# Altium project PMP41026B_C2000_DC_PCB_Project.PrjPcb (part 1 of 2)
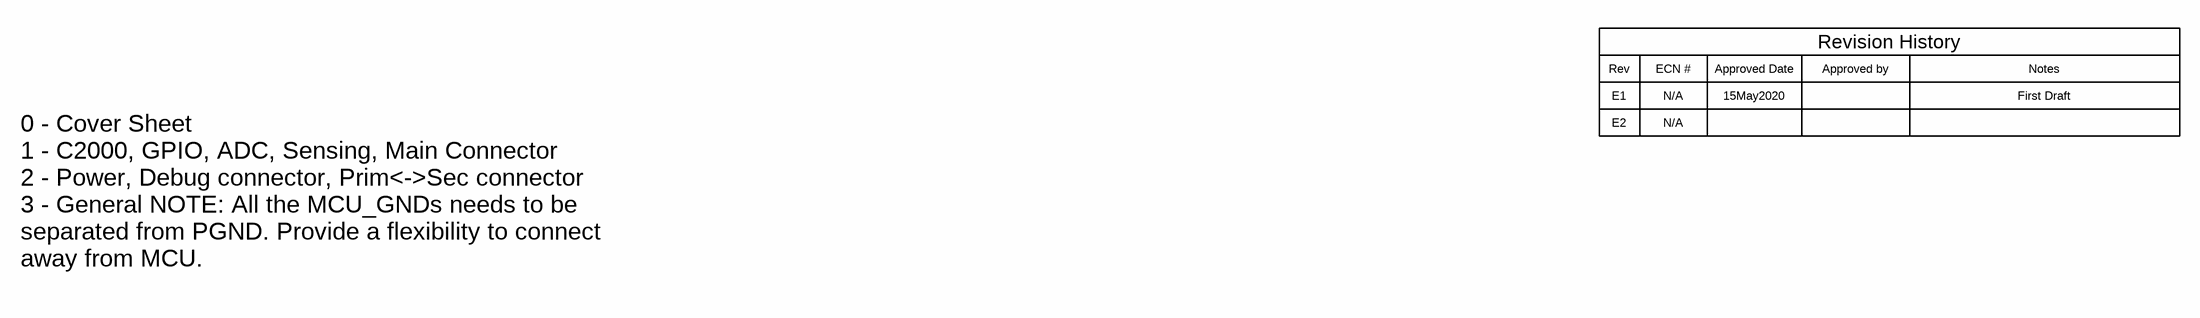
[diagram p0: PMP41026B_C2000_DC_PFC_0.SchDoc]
CopyrightYear: 2024; PCB_Layout: Richard Yin; PCB_Rev: B; PRJ_Customer: Public Release; PRJ_Engineer: Enter name of project lead; PRJ_Number: PMP41026B; PRJ_Title: Change in menu Project|Project Options|Parameters; SCH_Rev: B; TechSupport: http://www.ti.com/support; TID: N/A
5 sheets, 261 parts. Net scope: global (net labels, ports and power ports of the same name join across sheets).
Board file: PMP41026B_C2000_DC.PcbDoc
Sheets:
  PMP41026B_C2000_DC_PFC_0.SchDoc
  PMP41026B_C2000_DC_PFC_1.SchDoc
  PMP41026B_C2000_DC_PFC_2.SchDoc
  PMP41026B_C2000_DC_LLC_Control.SchDoc
  PMP41026B_C2000_DC_LLC_F280039C.SchDoc

## Sheet PMP41026B_C2000_DC_PFC_0.SchDoc: Cover Sheet
size 431 x 279 mm; Date: Not shown in title block; ApprovedBy: Not shown in title block; CheckedBy: Not shown in title block; Author: Not shown in title block; CompanyName: Not shown in title block; DrawnBy: San Chen; Engineer: Not shown in title block; Organization: Not shown in title block; Address1: Not shown in title block; Address2: Not shown in title block; Address3: Not shown in title block; Address4: Not shown in title block; DocumentNumber: 1; Revision: Use project parameter SCH_Rev; SheetNumber: 1; SheetTotal: 9; PageSetup: Record=PageOptions¦CenterHorizontal=True¦CenterVertical=True¦PrintScale=1.00¦XCorrection=1.00¦YCorrection=1.00¦PrintKind=0¦BorderSize=5000000¦LeftOffset=0¦BottomOffset=0¦Orientation=2¦PaperLength=1000¦PaperWidth=1000¦Scale=100¦PaperSource=15¦PrintQuality=600¦MediaType=1¦DitherType=10¦PaperKind=Letter¦PrintScaleMode=1

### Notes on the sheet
- Rev
- E1
- ECN #
- N/A
- Approved Date
- 15May2020
- Approved by
- Revision History
- Notes
- First Draft
- E2
- 0 - Cover Sheet
  1 - C2000, GPIO, ADC, Sensing, Main Connector
  2 - Power, Debug connector, Prim<->Sec connector
  3 - General NOTE: All the MCU_GNDs needs to be separated from PGND. Provide a flexibility to connect away from MCU.

## Sheet PMP41026B_C2000_DC_PFC_1.SchDoc: ADC
size 431 x 279 mm; Date: Not shown in title block; ApprovedBy: Not shown in title block; CheckedBy: Not shown in title block; Author: Not shown in title block; CompanyName: Not shown in title block; DrawnBy: San Chen; Engineer: Not shown in title block; Organization: Not shown in title block; Address1: Not shown in title block; Address2: Not shown in title block; Address3: Not shown in title block; Address4: Not shown in title block; DocumentNumber: 2; Revision: Use project parameter SCH_Rev; SheetNumber: 2; SheetTotal: 5; PageSetup: Record=PageOptions¦CenterHorizontal=True¦CenterVertical=True¦PrintScale=1.00¦XCorrection=1.00¦YCorrection=1.00¦PrintKind=0¦BorderSize=5000000¦LeftOffset=0¦BottomOffset=0¦Orientation=2¦PaperLength=1000¦PaperWidth=1000¦Scale=100¦PaperSource=15¦PrintQuality=600¦MediaType=1¦DitherType=10¦PaperKind=Letter¦PrintScaleMode=1
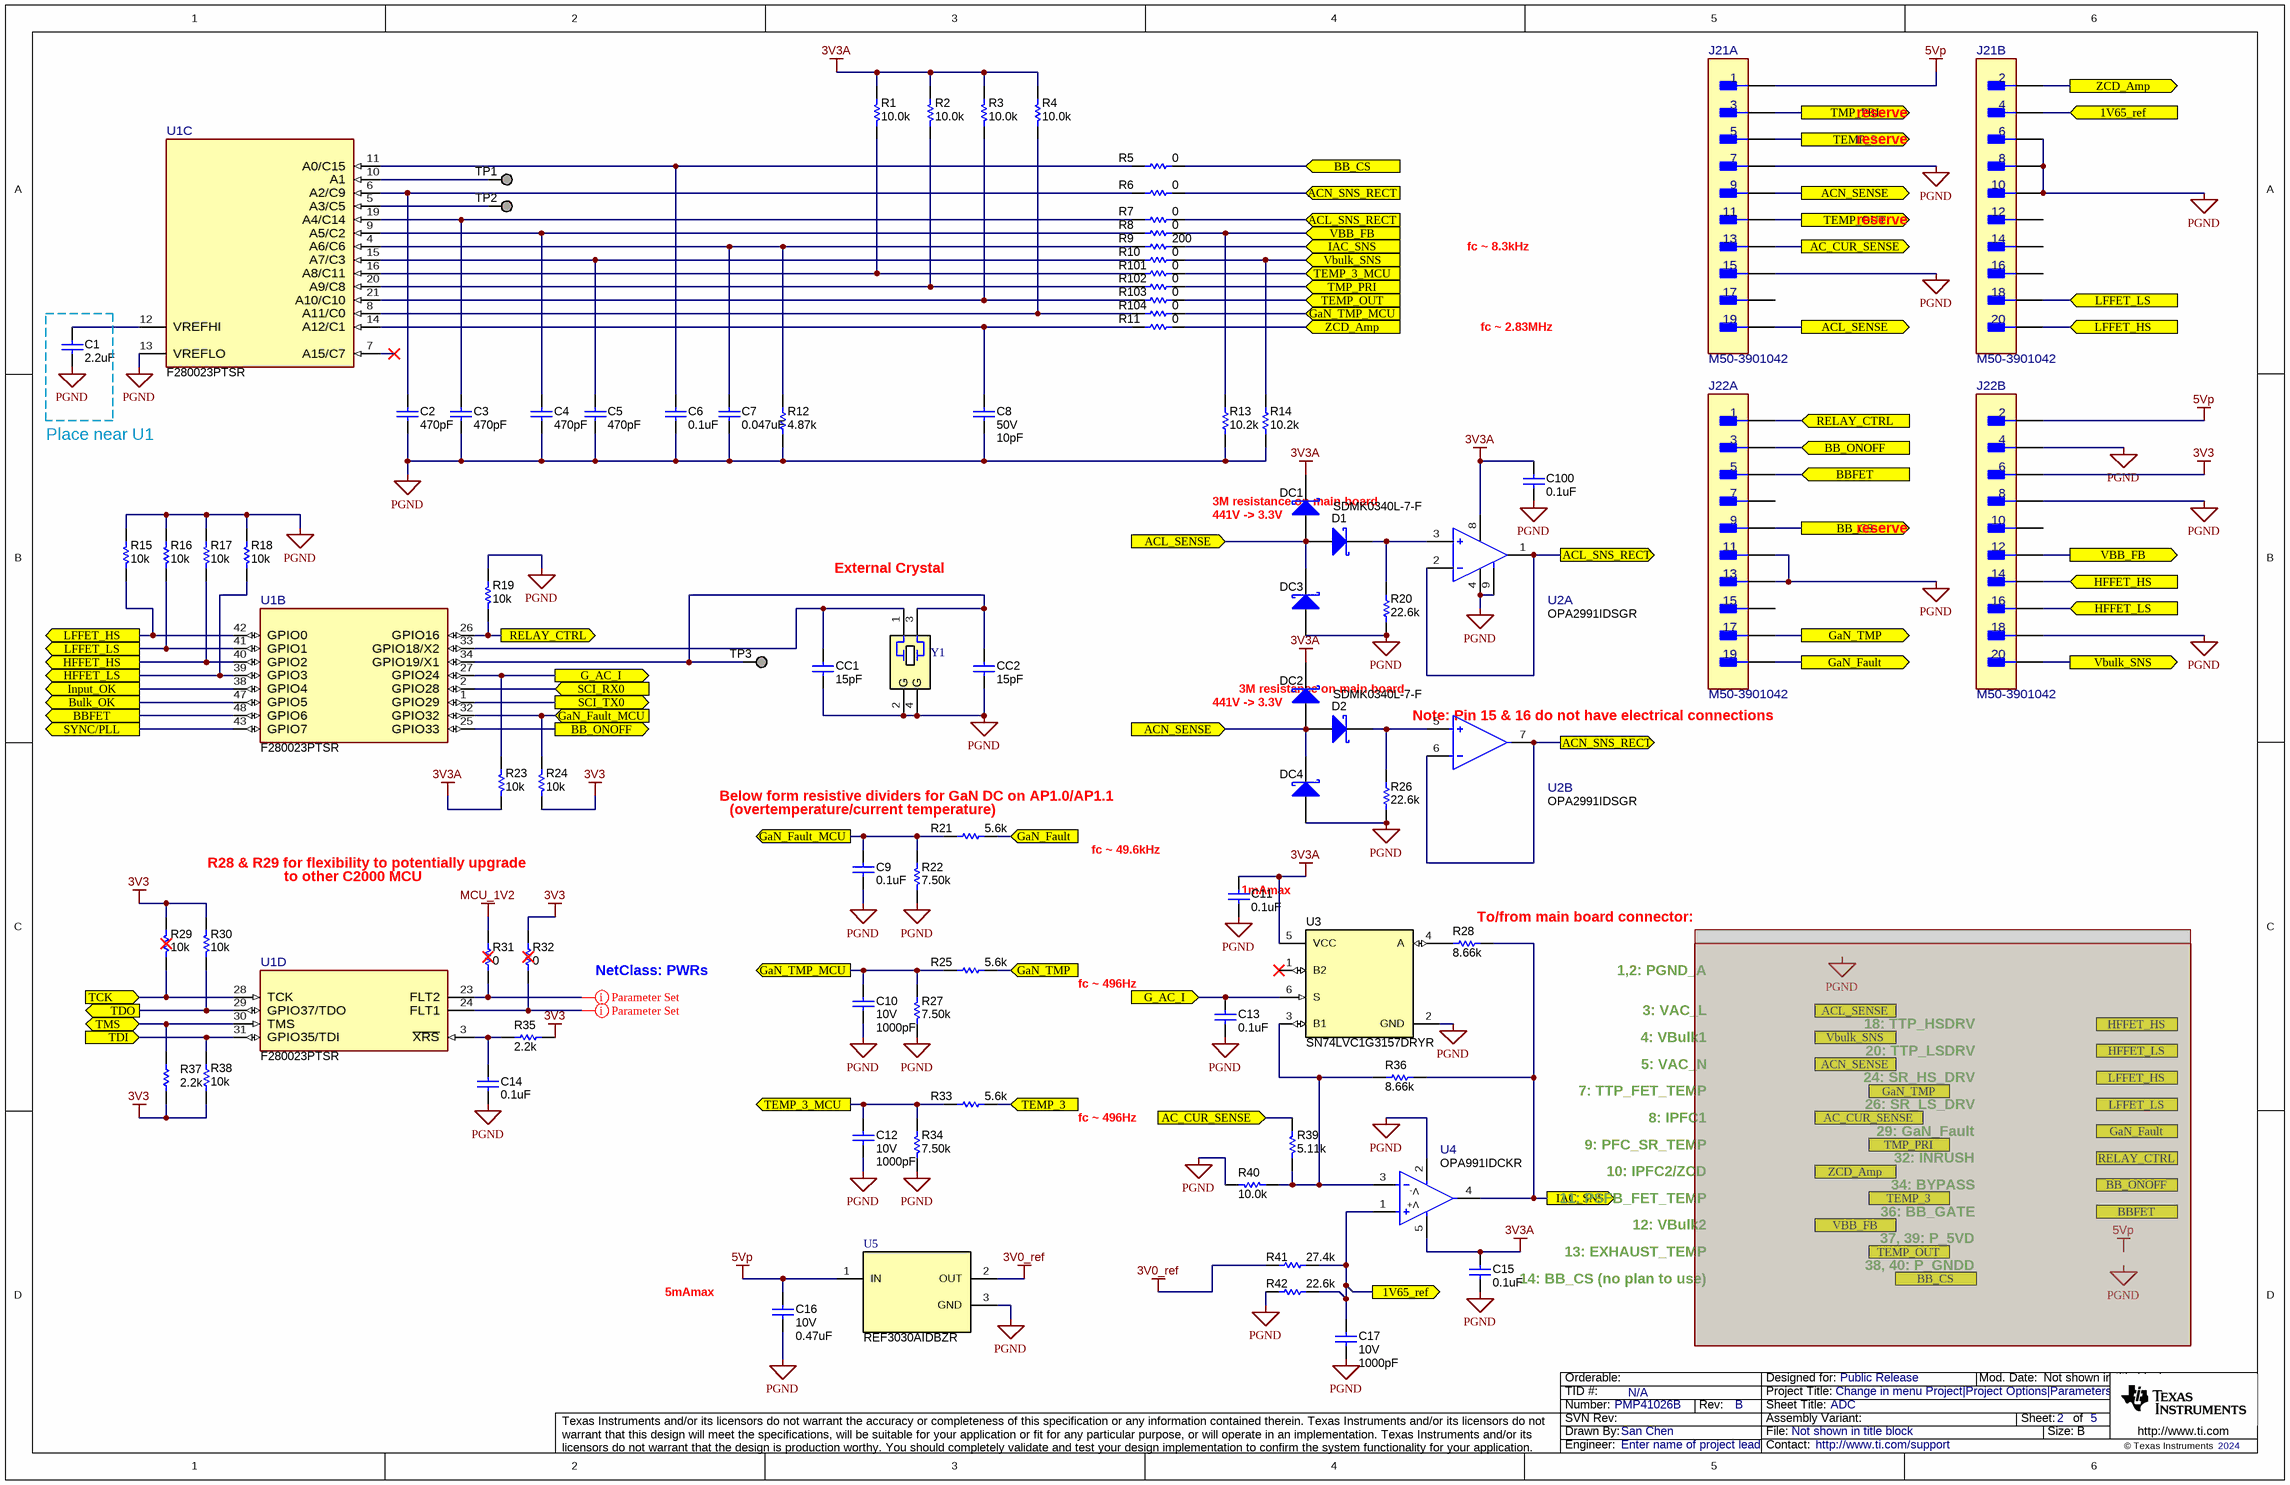
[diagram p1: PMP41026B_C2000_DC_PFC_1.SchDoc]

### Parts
C1  ValueDisplayed: 2.2uF  [0603]  (hidden comment: C0603C225K8PACTU)
C2  ValueDisplayed: 470pF  [0402]  (hidden comment: CGA2B2X7R1H471K050BA)
C3  ValueDisplayed: 470pF  [0402]  (hidden comment: CGA2B2X7R1H471K050BA)
C4  ValueDisplayed: 470pF  [0402]  (hidden comment: CGA2B2X7R1H471K050BA)
C5  ValueDisplayed: 470pF  [0402]  (hidden comment: CGA2B2X7R1H471K050BA)
C6  ValueDisplayed: 0.1uF  [0402]  (hidden comment: GRM155R60J104KA01D)
C7  ValueDisplayed: 0.047uF  [0402]  (hidden comment: C1005X5R1A473K050BA)
C8  VDC_V: 50V  ValueDisplayed: 10pF  [0402]  (hidden comment: 04025U100CAT2A)
C9  ValueDisplayed: 0.1uF  [0402]  (hidden comment: GRM155R60J104KA01D)
C10  VDC_V: 10V  ValueDisplayed: 1000pF  [0402]  (hidden comment: GRM155R61A102KA01D)
C11  ValueDisplayed: 0.1uF  [0402]  (hidden comment: GRM155R71A104KA01D)
C12  VDC_V: 10V  ValueDisplayed: 1000pF  [0402]  (hidden comment: GRM155R61A102KA01D)
C13  ValueDisplayed: 0.1uF  [0402]  (hidden comment: GCM155R71C104KA55D)
C14  ValueDisplayed: 0.1uF  [0402]  (hidden comment: GRM155R60J104KA01D)
C15  ValueDisplayed: 0.1uF  [0402]  (hidden comment: GRM155R60J104KA01D)
C16  VDC_V: 10V  ValueDisplayed: 0.47uF  [0402]  (hidden comment: GCM155C71A474KE36D)
C17  VDC_V: 10V  ValueDisplayed: 1000pF  [0402]  (hidden comment: GRM155R61A102KA01D)
C100  ValueDisplayed: 0.1uF  [0402]  (hidden comment: GRM155R71A104KA01D)
CC1  ValueDisplayed: 15pF  [0402]  (hidden comment: 885012005056)
CC2  ValueDisplayed: 15pF  [0402]  (hidden comment: 885012005056)
D1  SDMK0340L-7-F  [SOD-323]
D2  SDMK0340L-7-F  [SOD-323]
DC1  SDMK0340L-7-F  [SOD-323]  (value not drawn)
DC2  SDMK0340L-7-F  [SOD-323]  (value not drawn)
DC3  SDMK0340L-7-F  [SOD-323]  (value not drawn)
DC4  SDMK0340L-7-F  [SOD-323]  (value not drawn)
J21  M50-3901042  [FP-M50-3901042_HDR20-MFG]  (parts A,B of 2)
J22  M50-3901042  [FP-M50-3901042_HDR20-MFG]  (parts A,B of 2)
R1  ValueDisplayed: 10.0k  [0402]  (hidden comment: CRCW040210K0FKED)
R2  ValueDisplayed: 10.0k  [0402]  (hidden comment: CRCW040210K0FKED)
R3  ValueDisplayed: 10.0k  [0402]  (hidden comment: CRCW040210K0FKED)
R4  ValueDisplayed: 10.0k  [0402]  (hidden comment: CRCW040210K0FKED)
R5  ValueDisplayed: 0  [0402]  (hidden comment: CRCW04020000Z0ED)
R6  ValueDisplayed: 0  [0402]  (hidden comment: CRCW04020000Z0ED)
R7  ValueDisplayed: 0  [0402]  (hidden comment: CRCW04020000Z0ED)
R8  ValueDisplayed: 0  [0402]  (hidden comment: CRCW04020000Z0ED)
R9  ValueDisplayed: 200  [0402]  (hidden comment: CRCW0402200RJNED)
R10  ValueDisplayed: 0  [0402]  (hidden comment: CRCW04020000Z0ED)
R11  ValueDisplayed: 0  [0402]  (hidden comment: CRCW04020000Z0ED)
R12  ValueDisplayed: 4.87k  [0402]  (hidden comment: ERA-2AEB4871X)
R13  ValueDisplayed: 10.2k  [0402]  (hidden comment: CRCW040210K2FKED)
R14  ValueDisplayed: 10.2k  [0402]  (hidden comment: CRCW040210K2FKED)
R15  ValueDisplayed: 10k  [0402]  (hidden comment: CRCW040210K0JNED)
R16  ValueDisplayed: 10k  [0402]  (hidden comment: CRCW040210K0JNED)
R17  ValueDisplayed: 10k  [0402]  (hidden comment: CRCW040210K0JNED)
R18  ValueDisplayed: 10k  [0402]  (hidden comment: CRCW040210K0JNED)
R19  ValueDisplayed: 10k  [0402]  (hidden comment: CRCW040210K0JNED)
R20  ValueDisplayed: 22.6k  [0402]  (hidden comment: CRCW040222K6FKED)
R21  ValueDisplayed: 5.6k  [0402]  (hidden comment: CRCW04025K60JNED)
R22  ValueDisplayed: 7.50k  [0402]  (hidden comment: CRCW04027K50FKED)
R23  ValueDisplayed: 10k  [0402]  (hidden comment: CRCW040210K0JNED)
R24  ValueDisplayed: 10k  [0402]  (hidden comment: CRCW040210K0JNED)
R25  ValueDisplayed: 5.6k  [0402]  (hidden comment: CRCW04025K60JNED)
R26  ValueDisplayed: 22.6k  [0402]  (hidden comment: CRCW040222K6FKED)
R27  ValueDisplayed: 7.50k  [0402]  (hidden comment: CRCW04027K50FKED)
R28  ValueDisplayed: 8.66k  [0402]  (hidden comment: CRCW04028K66FKED)
R29  ValueDisplayed: 10k  [0402]  (hidden comment: CRCW040210K0JNED)
R30  ValueDisplayed: 10k  [0402]  (hidden comment: CRCW040210K0JNED)
R31  ValueDisplayed: 0  [0402]  (hidden comment: CRCW04020000Z0ED)
R32  ValueDisplayed: 0  [0402]  (hidden comment: CRCW04020000Z0ED)
R33  ValueDisplayed: 5.6k  [0402]  (hidden comment: CRCW04025K60JNED)
R34  ValueDisplayed: 7.50k  [0402]  (hidden comment: CRCW04027K50FKED)
R35  ValueDisplayed: 2.2k  [0402]  (hidden comment: CRCW04022K20JNED)
R36  ValueDisplayed: 8.66k  [0402]  (hidden comment: CRCW04028K66FKED)
R37  ValueDisplayed: 2.2k  [0402]  (hidden comment: CRCW04022K20JNED)
R38  ValueDisplayed: 10k  [0402]  (hidden comment: CRCW040210K0JNED)
R39  ValueDisplayed: 5.11k  [0402]  (hidden comment: CRCW04025K11FKED)
R40  ValueDisplayed: 10.0k  [0402]  (hidden comment: CRCW040210K0FKED)
R41  ValueDisplayed: 27.4k  [0402]  (hidden comment: CRCW040227K4FKED)
R42  ValueDisplayed: 22.6k  [0402]  (hidden comment: CRCW040222K6FKED)
R101  ValueDisplayed: 0  [0402]  (hidden comment: CRCW04020000Z0ED)
R102  ValueDisplayed: 0  [0402]  (hidden comment: CRCW04020000Z0ED)
R103  ValueDisplayed: 0  [0402]  (hidden comment: CRCW04020000Z0ED)
R104  ValueDisplayed: 0  [0402]  (hidden comment: CRCW04020000Z0ED)
TP1  TP_H0.45P0.75  [TP_H045P075]  (value not drawn)  (no BOM)
TP2  TP_H0.45P0.75  [TP_H045P075]  (value not drawn)  (no BOM)
TP3  TP_H0.45P0.75  [TP_H045P075]  (value not drawn)  (no BOM)
U1  F280023PTSR  [PT0048A-IPC_C]  (parts B,C,D of 4)
U2  OPA2991IDSGR  [DSG0008A-MFG]  (parts A,B of 2)
U3  SN74LVC1G3157DRYR  [DRY0006A]
U4  OPA991IDCKR  [DCK0005A-MFG]
U5  REF3030AIDBZR  [DBZ0003A_N]
Y1  ECS-200-18-30B-AGN-TR  [ECS_ECX-53B]  (value not drawn)

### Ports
1V65_ref (in), 1V65_ref (out), AC_CUR_SENSE (in), AC_CUR_SENSE (out), ACL_SENSE (in), ACL_SENSE (out), ACL_SNS_RECT (in), ACL_SNS_RECT (out), ACN_SENSE (in), ACN_SENSE (out), ACN_SNS_RECT (in), ACN_SNS_RECT (out), BB_CS (in), BB_CS (out), BB_ONOFF (in), BB_ONOFF (out), BBFET (in), BBFET (out), Bulk_OK (out), G_AC_I (in), G_AC_I (out), GaN_Fault (in), GaN_Fault (out), GaN_Fault_MCU (in), GaN_Fault_MCU (out), GaN_TMP (in), GaN_TMP (out), GaN_TMP_MCU (in), GaN_TMP_MCU (out), HFFET_HS (in), HFFET_HS (out), HFFET_LS (in), HFFET_LS (out), IAC_SNS (in), IAC_SNS (out), Input_OK (out), LFFET_HS (in), LFFET_HS (out), LFFET_LS (in), LFFET_LS (out), RELAY_CTRL (in), RELAY_CTRL (out), SCI_RX0 (in), SCI_TX0 (out), SYNC/PLL (out), TCK (in), TDI (in), TDO (out), TEMP_3 (in), TEMP_3 (out), TEMP_3_MCU (in), TEMP_3_MCU (out), TEMP_OUT (in), TEMP_OUT (out), TMP_PRI (in), TMP_PRI (out), TMS (bidir), VBB_FB (in), VBB_FB (out), Vbulk_SNS (in), Vbulk_SNS (out), ZCD_Amp (in), ZCD_Amp (out)

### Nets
3V0_ref: R41.1 U5.2(OUT)
3V3: J22.6 R24.2 R29.1 R30.1 R32.2 R35.1 R37.1 R38.2
3V3A: C11.1 C15.2 C100.1 DC1.1(K) DC2.1(K) R1.2 R2.2 R3.2 R4.2 R23.2 U2.8(V+) U3.5(VCC) U4.5(V+)
5Vp: C16.1 J21.1 J22.2 U5.1(IN)
MCU_1V2: R31.2
PGND: C1.1 C2.2 C3.2 C4.2 C5.2 C6.1 C7.2 C8.2 C9.1 C10.2 C11.2 C12.2 C13.2 C14.1 C15.1 C16.2 C17.2 C100.2 CC1.2 CC2.2 DC3.2(A) DC4.2(A) J21.6 J21.7 J21.8 J21.10 J21.15 J22.4 J22.8 J22.11 J22.13 J22.18 R12.1 R13.1 R14.1 R15.1 R16.1 R17.1 R18.1 R19.1 R20.1 R22.1 R26.1 R27.1 R34.1 R40.2 R42.2 U1.13(VREFLO) U2.4(V-) U2.9(Thermal_Pad) U3.2(GND) U4.2(V-) U5.3(GND) Y1.2(GND) Y1.4(GND)
1V65_ref: C17.1 J21.4 R41.2 R42.1 U4.1(IN+) ; port 1V65_ref
AC_CUR_SENSE: J21.13 R39.1 ; port AC_CUR_SENSE
ACL_SENSE: D1.2(A) DC1.2(A) DC3.1(K) J21.19 ; port ACL_SENSE
ACL_SNS_RECT: R7.2 U2.1(OUT1) U2.2(IN1-) ; port ACL_SNS_RECT
ACN_SENSE: D2.2(A) DC2.2(A) DC4.1(K) J21.9 ; port ACN_SENSE
ACN_SNS_RECT: R6.2 U2.6(IN2-) U2.7(OUT2) ; port ACN_SNS_RECT
BB_CS: J22.9 R5.2 ; port BB_CS
BB_ONOFF: J22.3 U1.25(GPIO33) ; port BB_ONOFF
BBFET: J22.5 U1.48(GPIO6) ; port BBFET
Bulk_OK: U1.47(GPIO5) ; port Bulk_OK
G_AC_I: C13.1 R23.1 U1.27(GPIO24) U3.6(S) ; port G_AC_I
GaN_Fault: J22.19 R21.2 ; port GaN_Fault
GaN_Fault_MCU: C9.2 R21.1 R22.2 R24.1 U1.32(GPIO32) ; port GaN_Fault_MCU
GaN_TMP: J22.17 R25.2 ; port GaN_TMP
GaN_TMP_MCU: C10.1 R25.1 R27.2 R104.2 ; port GaN_TMP_MCU
HFFET_HS: J22.14 R17.2 U1.40(GPIO2) ; port HFFET_HS
HFFET_LS: J22.16 R18.2 U1.39(GPIO3) ; port HFFET_LS
IAC_SNS: R9.2 R28.2 R36.2 U4.4(OUT) ; port IAC_SNS
Input_OK: U1.38(GPIO4) ; port Input_OK
LFFET_HS: J21.20 R15.2 U1.42(GPIO0) ; port LFFET_HS
LFFET_LS: J21.18 R16.2 U1.41(GPIO1) ; port LFFET_LS
RELAY_CTRL: J22.1 R19.2 U1.26(GPIO16) ; port RELAY_CTRL
SCI_RX0: U1.2(GPIO28) ; port SCI_RX0
SCI_TX0: U1.1(GPIO29) ; port SCI_TX0
SYNC/PLL: U1.43(GPIO7) ; port SYNC/PLL
TCK: R29.2 U1.28(TCK) ; port TCK
TDI: R38.1 U1.31(GPIO35/TDI) ; port TDI
TDO: R30.2 U1.29(GPIO37/TDO) ; port TDO
TEMP_3: J21.5 R33.2 ; port TEMP_3
TEMP_3_MCU: C12.1 R33.1 R34.2 R101.2 ; port TEMP_3_MCU
TEMP_OUT: J21.11 R103.2 ; port TEMP_OUT
TMP_PRI: J21.3 R102.2 ; port TMP_PRI
TMS: R37.2 U1.30(TMS) ; port TMS
VBB_FB: J22.12 R8.2 R13.2 ; port VBB_FB
Vbulk_SNS: J22.20 R10.2 R14.2 ; port Vbulk_SNS
ZCD_Amp: J21.2 R11.2 ; port ZCD_Amp
NetC1_2: C1.2 U1.12(VREFHI)
NetC2_1: C2.1 R6.1 U1.6(A2/C9)
NetC3_1: C3.1 R7.1 U1.19(A4/C14)
NetC4_1: C4.1 R8.1 U1.9(A5/C2)
NetC5_1: C5.1 R10.1 U1.15(A7/C3)
NetC6_2: C6.2 R5.1 U1.11(A0/C15)
NetC7_1: C7.1 R9.1 R12.2 U1.4(A6/C6)
NetC8_1: C8.1 R11.1 U1.14(A12/C1)
NetC14_2: C14.2 R35.2 U1.3(~{XRS})
NetCC1_1: CC1.1 U1.33(GPIO18/X2) Y1.1
NetCC2_1: CC2.1 TP3.1 U1.34(GPIO19/X1) Y1.3
NetD1_1: D1.1(K) R20.2 U2.3(IN1+)
NetD2_1: D2.1(K) R26.2 U2.5(IN2+)
NetR1_1: R1.1 R101.1 U1.16(A8/C11)
NetR2_1: R2.1 R102.1 U1.20(A9/C8)
NetR3_1: R3.1 R103.1 U1.21(A10/C10)
NetR4_1: R4.1 R104.1 U1.8(A11/C0)
NetR28_1: R28.1 U3.4(A)
NetR31_1: R31.1 U1.23(FLT2)
NetR32_1: R32.1 U1.24(FLT1)
NetR36_1: R36.1 R39.2 R40.1 U3.3(B1) U4.3(IN-)
NetTP1_1: TP1.1 U1.10(A1)
NetTP2_1: TP2.1 U1.5(A3/C5)

Not connected (* = marked no-connect by the designer): J21 12 14 16 17; J22 7 10 15; U1 7(A15/C7)*; U3 1(B2)*

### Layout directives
net class PWRs: NetR31_1, NetR32_1

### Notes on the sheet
- reserve
- fc ~ 8.3kHz
- fc ~ 2.83MHz
- Place near U1
- 3M resistance on main board
- External Crystal
- 441V -> 3.3V
- (near J22) Note: Pin 15 & 16 do not have electrical connections
- (near R21) (overtemperature/current temperature)
- (near R21) Below form resistive dividers for GaN DC on AP1.0/AP1.1
- to other C2000 MCU
- R28 & R29 for flexibility to potentially upgrade
- (near R21) fc ~ 49.6kHz
- 1mAmax
- NetClass: PWRs
- To/from main board connector:
- 1,2: PGND_A
- (near R25) fc ~ 496Hz
- 3: VAC_L
- 4: VBulk1
- 18: TTP_HSDRV
- 5: VAC_N
- 7: TTP_FET_TEMP
- 20: TTP_LSDRV
- 24: SR_HS_DRV
- 26: SR_LS_DRV
- (near R33) fc ~ 496Hz
- 8: IPFC1
- 9: PFC_SR_TEMP
- 10: IPFC2/ZCD
- 32: INRUSH
- 29: GaN_Fault
- 11: PSFB_FET_TEMP
- 12: VBulk2
- 34: BYPASS
- 36: BB_GATE
- 37, 39: P_5VD
- (near C16) 5mAmax
- 13: EXHAUST_TEMP
- 14: BB_CS (no plan to use)
- 38, 40: P_GNDD

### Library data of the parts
C1 = CMP-0006906-5: CAP, CERM, 2.2 uF, 10 V, +/- 10%, X5R, 0603; Manufacturer: Kemet; TaMin_C: -55°C; Polarized: N; SizeAreaWB_mm2: 4.68; Value1: Unknown; U/M: EA; Value: 2.2uF; TaMax_C: 85°C; SizeZ_mm: 1; SizeX_mm: 1.6; SizeY_mm: 0.8; Value2: 10V; SizeArea_mm2: 1.28; CompType: Capacitor; Cap_F: 2.2µF; AEC Category: Q200
C2-C5 = CMP-0006320-2: CAP, CERM, 470 pF, 50 V, +/- 10%, X7R, AEC-Q200 Grade 1, 0402; Manufacturer: TDK; TaMin_C: -55°C; ESR_ohm: 4.96489; Polarized: N; SizeAreaWB_mm2: 3; Value1: 4.96489 ohm; U/M: EA; Value: 470pF; TaMax_C: 125°C; SizeZ_mm: 0.6; SizeX_mm: 1; SizeY_mm: 0.5; Value2: 50V; CompType: Capacitor; AEC Qualified: Y; IRMS_A: 2.28414dA; AEC Category: Q200
C6 C9 C14 C15 = CMP-0006531-2: CAP, CERM, 0.1 uF, 6.3 V, +/- 10%, X5R, 0402; Manufacturer: MuRata; Polarized: N; Value: 0.1uF; U/M: EA; Cap_F: 100nF; Value1: Unknown; VDC_V: 6.3V; TaMin_C: -55°C; TaMax_C: 85°C; AEC Category: Q200; SizeArea_mm2: 0.5; SizeAreaWB_mm2: 3; SizeX_mm: 1; SizeZ_mm: 0.6
C7 = CMP-0006266-2: CAP, CERM, 0.047 uF, 10 V, +/- 10%, X5R, 0402; Manufacturer: TDK; Polarized: N; U/M: EA; Cap_F: 47nF; Value1: Unknown; VDC_V: 10V; TaMin_C: -55°C; TaMax_C: 85°C; SizeArea_mm2: 0.5; SizeAreaWB_mm2: 3; SizeX_mm: 1; SizeZ_mm: 0.6; AEC Category: Q200
C8 = CMP-0064911-2: CAP, CERM, 10 pF, 50 V,+/- 2.5%, C0G/NP0, AEC-Q200 Grade 1, 0402; Manufacturer: AVX; TaMin_C: -55°C; Polarized: N; SizeAreaWB_mm2: 3; Value1: Unknown; U/M: EA; Value: 10pF; TaMax_C: 125°C; SizeZ_mm: 0.6; SizeX_mm: 1; SizeY_mm: 0.5; AEC Qualified: Y; AEC Category: Q200
C10 C12 C17 = CMP-0006560-2: CAP, CERM, 1000 pF, 10 V, +/- 10%, X5R, 0402; Manufacturer: MuRata; TaMin_C: -55°C; Polarized: N; SizeAreaWB_mm2: 3; Value1: Unknown; U/M: EA; Value: 1000pF; TaMax_C: 85°C; SizeZ_mm: 0.6; SizeX_mm: 1; SizeY_mm: 0.5; Cap_F: 1nF; AEC Category: Q200
C11 C100 = CMP-0006629-2: CAP, CERM, 0.1 uF, 10 V, +/- 10%, X7R, 0402; Manufacturer: MuRata; Polarized: N; Value: 0.1uF; U/M: EA; Cap_F: 100nF; Value1: Unknown; VDC_V: 10V; TaMin_C: -55°C; TaMax_C: 125°C; SizeArea_mm2: 0.5; SizeAreaWB_mm2: 3; SizeX_mm: 1; SizeZ_mm: 0.6; AEC Category: Q200
C13 = CMP-0006351-2: CAP, CERM, 0.1 uF, 16 V, +/- 10%, X7R, 0402; Manufacturer: MuRata; Polarized: N; Value: 0.1uF; U/M: EA; Cap_F: 100nF; Value1: Unknown; VDC_V: 16V; TaMin_C: -55°C; TaMax_C: 125°C; SizeArea_mm2: 0.5; SizeAreaWB_mm2: 3; SizeX_mm: 1; SizeZ_mm: 0.6; AEC Category: Q200
C16 = CMP-0064967-2: CAP, CERM, 0.47 uF, 10 V,+/- 10%, X7S, 0402; Manufacturer: MuRata; TaMin_C: -55°C; Polarized: N; SizeAreaWB_mm2: 3; Value1: Unknown; U/M: EA; Value: 0.47uF; TaMax_C: 125°C; SizeZ_mm: 0.6; SizeX_mm: 1; SizeY_mm: 0.5; Cap_F: 470nF; AEC Category: Q200
CC1 CC2 = CMP-0006216-2: CAP, CERM, 15 pF, 50 V, +/- 5%, C0G/NP0, 0402; Manufacturer: Wurth Elektronik; Polarized: N; Value: 15pF; U/M: EA; Value1: Unknown; VDC_V: 50V; TaMin_C: -55°C; TaMax_C: 125°C; AEC Category: Q200; SizeArea_mm2: 0.5; SizeAreaWB_mm2: 3; SizeX_mm: 1; SizeZ_mm: 0.6
D1 D2 DC1-DC4 = CMP-0028573-2: Diode, Schottky, 40 V, 0.03 A, SOD-323; Manufacturer: Diodes Inc.; Vf_V: 1V; SizeArea_mm2: 3.645; Vr_V: 40V; SizeAreaWB_mm2: 8.695; Io_A: 30mA; Value1: 0.03A; Green_Lifecycle: Not Set; SizeZ_mm: 1; SizeY_mm: 1.35; Value: 40V; SizeX_mm: 2.7; AEC Category: Q101; Green_REACh: Incomplete
J21 J22 = CMP-0122579-1: Connector Header Through Hole, Right Angle 20 position 0.050" (1.27mm); Manufacturer: Harwin; ContactFinish: Gold,Nickel; Current_A: 1A; Row_Count: 2; AEC Qualified: No; Conn Gender: Male; Conn Orientation: Horizontal; SizeZ_mm: 3.55mm
R1-R4 R40 = CMP-0025958-3: RES, 10.0 k, 1%, 0.063 W, AEC-Q200 Grade 0, 0402; Manufacturer: Vishay-Dale; Value: 10.0k; Res_ohm: 10k; Value_Code: 10k0; Power_W: 63mW; Value2: 0.063W; VDC_V: 50V; TempCo: 100 ppm/C; SizeArea_mm2: 0.5; SizeX_mm: 1; SizeZ_mm: 0.6; EIA_Code: E96; AEC Category: Q200; AEC Qualified: Y; AEC Grade: 0
R5-R8 R10 R11 R31 R32 R101-R104 = CMP-0026822-3: RES, 0, 5%, 0.063 W, AEC-Q200 Grade 0, 0402; Manufacturer: Vishay-Dale; Power_W: 63mW; TempCo: 200 ppm/C; Value_Code: 0000; Value: 0; EIA_Code: E24; SizeX_mm: 1; SizeY_mm: 0.5; SizeZ_mm: 0.6; Value2: 0.063W; AEC Qualified: Y; VDC_V: 50V; AEC Category: Q200
R9 = CMP-0026874-3: RES, 200, 5%, 0.063 W, AEC-Q200 Grade 0, 0402; Manufacturer: Vishay-Dale; Power_W: 63mW; TempCo: 200 ppm/C; Value_Code: 200R; Value: 200; EIA_Code: E24; SizeX_mm: 1; SizeY_mm: 0.5; SizeZ_mm: 0.6; Value2: 0.063W; AEC Qualified: Y; VDC_V: 50V; AEC Category: Q200; AEC Grade: 0
R12 = CMP-0026781-1: RES, 4.87 k, 0.1%, 0.062 W, AEC-Q200 Grade 0, 0402; Manufacturer: Panasonic; Value: 4.87k; Value_Code: 4k87; Power_W: 62mW; Value2: 0.062W; VDC_V: 25V; TempCo: 25 ppm/C; EIA_Code: E192; U/M: EA; AEC Category: Q200; AEC Qualified: Y; AEC Grade: 0; SizeArea_mm2: 0.5; SizeX_mm: 1; SizeZ_mm: 0.6
R13 R14 = CMP-0025959-3: RES, 10.2 k, 1%, 0.063 W, AEC-Q200 Grade 0, 0402; Manufacturer: Vishay-Dale; Power_W: 63mW; TempCo: 100 ppm/C; Value_Code: 10k2; Value: 10.2k; EIA_Code: E96; SizeX_mm: 1; SizeY_mm: 0.5; SizeZ_mm: 0.6; Value2: 0.063W; AEC Qualified: Y; VDC_V: 50V; AEC Category: Q200; AEC Grade: 0
R15-R19 R23 R24 R29 R30 R38 = CMP-0026825-5: RES, 10 k, 5%, 0.063 W, AEC-Q200 Grade 0, 0402; Manufacturer: Vishay-Dale; Value: 10k; Value_Code: 10k0; Power_W: 63mW; Value2: 0.063W; VDC_V: 50V; TempCo: 200 ppm/C; EIA_Code: E24; AEC Category: Q200; AEC Qualified: Y; AEC Grade: 0; SizeArea_mm2: 0.5; SizeX_mm: 1; SizeZ_mm: 0.6
R20 R26 R42 = CMP-0026179-2: RES, 22.6 k, 1%, 0.063 W, AEC-Q200 Grade 0, 0402; Manufacturer: Vishay-Dale; Power_W: 63mW; TempCo: 100 ppm/C; Value_Code: 22k6; Value: 22.6k; EIA_Code: E96; SizeX_mm: 1; SizeY_mm: 0.5; SizeZ_mm: 0.6; Value2: 0.063W; AEC Qualified: Y; VDC_V: 50V; AEC Category: Q200; AEC Grade: 0
R21 R25 R33 = CMP-0026952-5: RES, 5.6 k, 5%, 0.063 W, AEC-Q200 Grade 0, 0402; Manufacturer: Vishay-Dale; Power_W: 63mW; TempCo: 200 ppm/C; Value_Code: 5k60; Value: 5.6k; EIA_Code: E24; SizeX_mm: 1; SizeY_mm: 0.5; SizeZ_mm: 0.6; Value2: 0.063W; AEC Qualified: Y; VDC_V: 50V; AEC Category: Q200; AEC Grade: 0
R22 R27 R34 = CMP-0026555-2: RES, 7.50 k, 1%, 0.063 W, AEC-Q200 Grade 0, 0402; Manufacturer: Vishay-Dale; Value: 7.50k; Res_ohm: 7.5k; Value_Code: 7k50; Power_W: 63mW; Value2: 0.063W; VDC_V: 50V; TempCo: 100 ppm/C; SizeArea_mm2: 0.5; SizeX_mm: 1; SizeZ_mm: 0.6; EIA_Code: E96; AEC Category: Q200; AEC Qualified: Y; AEC Grade: 0
R28 R36 = CMP-0026591-2: RES, 8.66 k, 1%, 0.063 W, AEC-Q200 Grade 0, 0402; Manufacturer: Vishay-Dale; Power_W: 63mW; TempCo: 100 ppm/C; Value_Code: 8k66; Value: 8.66k; EIA_Code: E96; SizeX_mm: 1; SizeY_mm: 0.5; SizeZ_mm: 0.6; Value2: 0.063W; AEC Qualified: Y; VDC_V: 50V; AEC Category: Q200; AEC Grade: 0
R35 R37 = CMP-0026890-5: RES, 2.2 k, 5%, 0.063 W, AEC-Q200 Grade 0, 0402; Manufacturer: Vishay-Dale; Value: 2.2k; Value_Code: 2k20; Power_W: 63mW; Value2: 0.063W; VDC_V: 50V; TempCo: 200 ppm/C; EIA_Code: E24; AEC Category: Q200; AEC Qualified: Y; AEC Grade: 0; SizeArea_mm2: 0.5; SizeX_mm: 1; SizeZ_mm: 0.6
R39 = CMP-0026463-2: RES, 5.11 k, 1%, 0.063 W, AEC-Q200 Grade 0, 0402; Manufacturer: Vishay-Dale; Power_W: 63mW; TempCo: 100 ppm/C; Value_Code: 5k11; Value: 5.11k; EIA_Code: E96; SizeX_mm: 1; SizeY_mm: 0.5; SizeZ_mm: 0.6; Value2: 0.063W; AEC Qualified: Y; VDC_V: 50V; AEC Category: Q200; AEC Grade: 0
R41 = CMP-0026213-2: RES, 27.4 k, 1%, 0.063 W, AEC-Q200 Grade 0, 0402; Manufacturer: Vishay-Dale; Power_W: 63mW; TempCo: 100 ppm/C; Value_Code: 27k4; Value: 27.4k; EIA_Code: E96; SizeX_mm: 1; SizeY_mm: 0.5; SizeZ_mm: 0.6; Value2: 0.063W; AEC Qualified: Y; VDC_V: 50V; AEC Category: Q200; AEC Grade: 0
TP1-TP3 = CMP-0003719-1: Testpoint; Manufacturer: Texas Instruments; CompType: Pad
U1 = CMP-0088708-1: TMS320F28002x Microcontrollers; Manufacturer: Texas Instruments; Memory Type: FLASH; Number Of Timers/Counters: 3; Number Of I2C Channels: 2; Min Supply Voltage: 1.14V; Number Of Cores: 1; Number Of Adc Channels: 14; Memory Size: 64KBytes; Standoff Height: 0.05mm; Nominal Supply Current: 12-86mA; TaMax_C: +125°C; TaMin_C: -40°C; Data Bus Width: 32bits; Max Supply Voltage: 3.63V; Ram Size: 24KBytes; Interface: I2C,SPI,UART,CAN,LIN,SCI,Other; Frequency_Fixed: 100MHz; SizeZ_mm: 1.6mm; Core Architecture: C28x; Number Of I/Os: 18; AEC Qualified: No
U2 = CMP-0092447-1: 40-V, dual 4.5MHz, rail-to-rail input/output, low-offset-voltage, low-noise op amp 8-WSON -40 to 125; Manufacturer: Texas Instruments; Nominal Supply Current: 560uA; TJmax_C: +150°C; Standoff Height: 0mm; Max Supply Voltage: 40V; Response Time: 1us; TaMin_C: -40°C; Input Offset Voltage: 0.125mV; Output Current Per Channel: 75mA; SizeZ_mm: 0.8mm; Min Supply Voltage: 2.7V; Voltage Gain: 145dB; TaMax_C: +125°C; Min Dual Supply Voltage: 1.35V; AEC Qualified: No; Input Bias Current: 0.00001uA; Max Dual Supply Voltage: 20V; Number Of Channels: 2
U3 = CMP-0050995-4: 1-Channel, 2:1 Analog Switch, DRY0006A (USON-6); Manufacturer: Texas Instruments; CompType: IC; 3-State Output: No; AEC Category: Q200; AEC Qualified: N; Bits(#): 1; F @ Nom Voltage(Max)(Mhz): 150; ICC @ Nom Voltage(Max)(mA): 0.01; Input Type: CMOS/TTL; Logic: True; Mux Configuration: 1：2; Output Drive (IOL/IOH)(Max)(mA): 32/-32; Output Type: CMOS; Rating: Catalog; SizeArea_mm2: 1.45; SizeAreaWB_mm2: 4.9; SizeX_mm: 1.0; SizeZ_mm: 0.6; Switch Configuration: SPDT; Technology Family: LVC; tpd @ Nom Voltage(Max)(ns): 2,1.2,0.8,0.3; VCC(Max)(V): 5.5; VCC(Min)(V): 1.65; Voltage(Nom)(V): 1.8,2.5,3.3,5
U4 = CMP-0092514-1: General Purpose Amplifier Circuit Rail-to-Rail SC-70-5; Manufacturer: Texas Instruments; Min Supply Voltage: 2.7V; Gain Bandwidth: 4.5MHz; Standoff Height: 0mm; TJmax_C: +150°C; Output Current Per Channel: 75mA; Input Offset Voltage: 0.125mV; Input Bias Current: 0.00001uA; Response Time: 2.5us; Number Of Channels: 1; SizeZ_mm: 1.1mm; TaMin_C: -40°C; TaMax_C: +125°C; Min Dual Supply Voltage: 1.35V; Max Dual Supply Voltage: 20V; Max Supply Voltage: 40V; AEC Qualified: No; Nominal Supply Current: 560uA
U5 = CMP-0032499-1: 3.0 V, 50 ppm / degC, 50 uA Series (Bandgap) Voltage Reference, -40 to 125 degC, 3-pin SOT-23 (DBZ), Green (RoHS & no Sb/Br); Manufacturer: Texas Instruments; SubFamily: Series Voltage Reference; Temp Coeff(Typ)(ppm/ degree C): 20; Temp Coeff(Max)(ppm/ degree C): 50; Rating: Catalog
Y1 = CMP-0080365-2: Crystal, 20 MHz, 25 ppm, 18 pF, SMD; Manufacturer: ECS Inc.; Frequency Stability: 30 ppm; AEC Qualified: N; Frequency Tolerance: 25 ppm; AEC Category: Q200; TaMax_C: 85°C; Frequency_Fixed: 20MHz; TaMin_C: -40°C; Load Capacitance: 18 pF

## Sheet PMP41026B_C2000_DC_PFC_2.SchDoc: Connector+IO
size 431 x 279 mm; Date: Not shown in title block; ApprovedBy: Not shown in title block; CheckedBy: Not shown in title block; Author: Not shown in title block; CompanyName: Not shown in title block; DrawnBy: San Chen; Engineer: Not shown in title block; Organization: Not shown in title block; Address1: Not shown in title block; Address2: Not shown in title block; Address3: Not shown in title block; Address4: Not shown in title block; DocumentNumber: 3; Revision: Use project parameter SCH_Rev; SheetNumber: 3; SheetTotal: 5; PageSetup: Record=PageOptions¦CenterHorizontal=True¦CenterVertical=True¦PrintScale=1.00¦XCorrection=1.00¦YCorrection=1.00¦PrintKind=0¦BorderSize=5000000¦LeftOffset=0¦BottomOffset=0¦Orientation=2¦PaperLength=1000¦PaperWidth=1000¦Scale=100¦PaperSource=15¦PrintQuality=600¦MediaType=1¦DitherType=10¦PaperKind=Letter¦PrintScaleMode=1
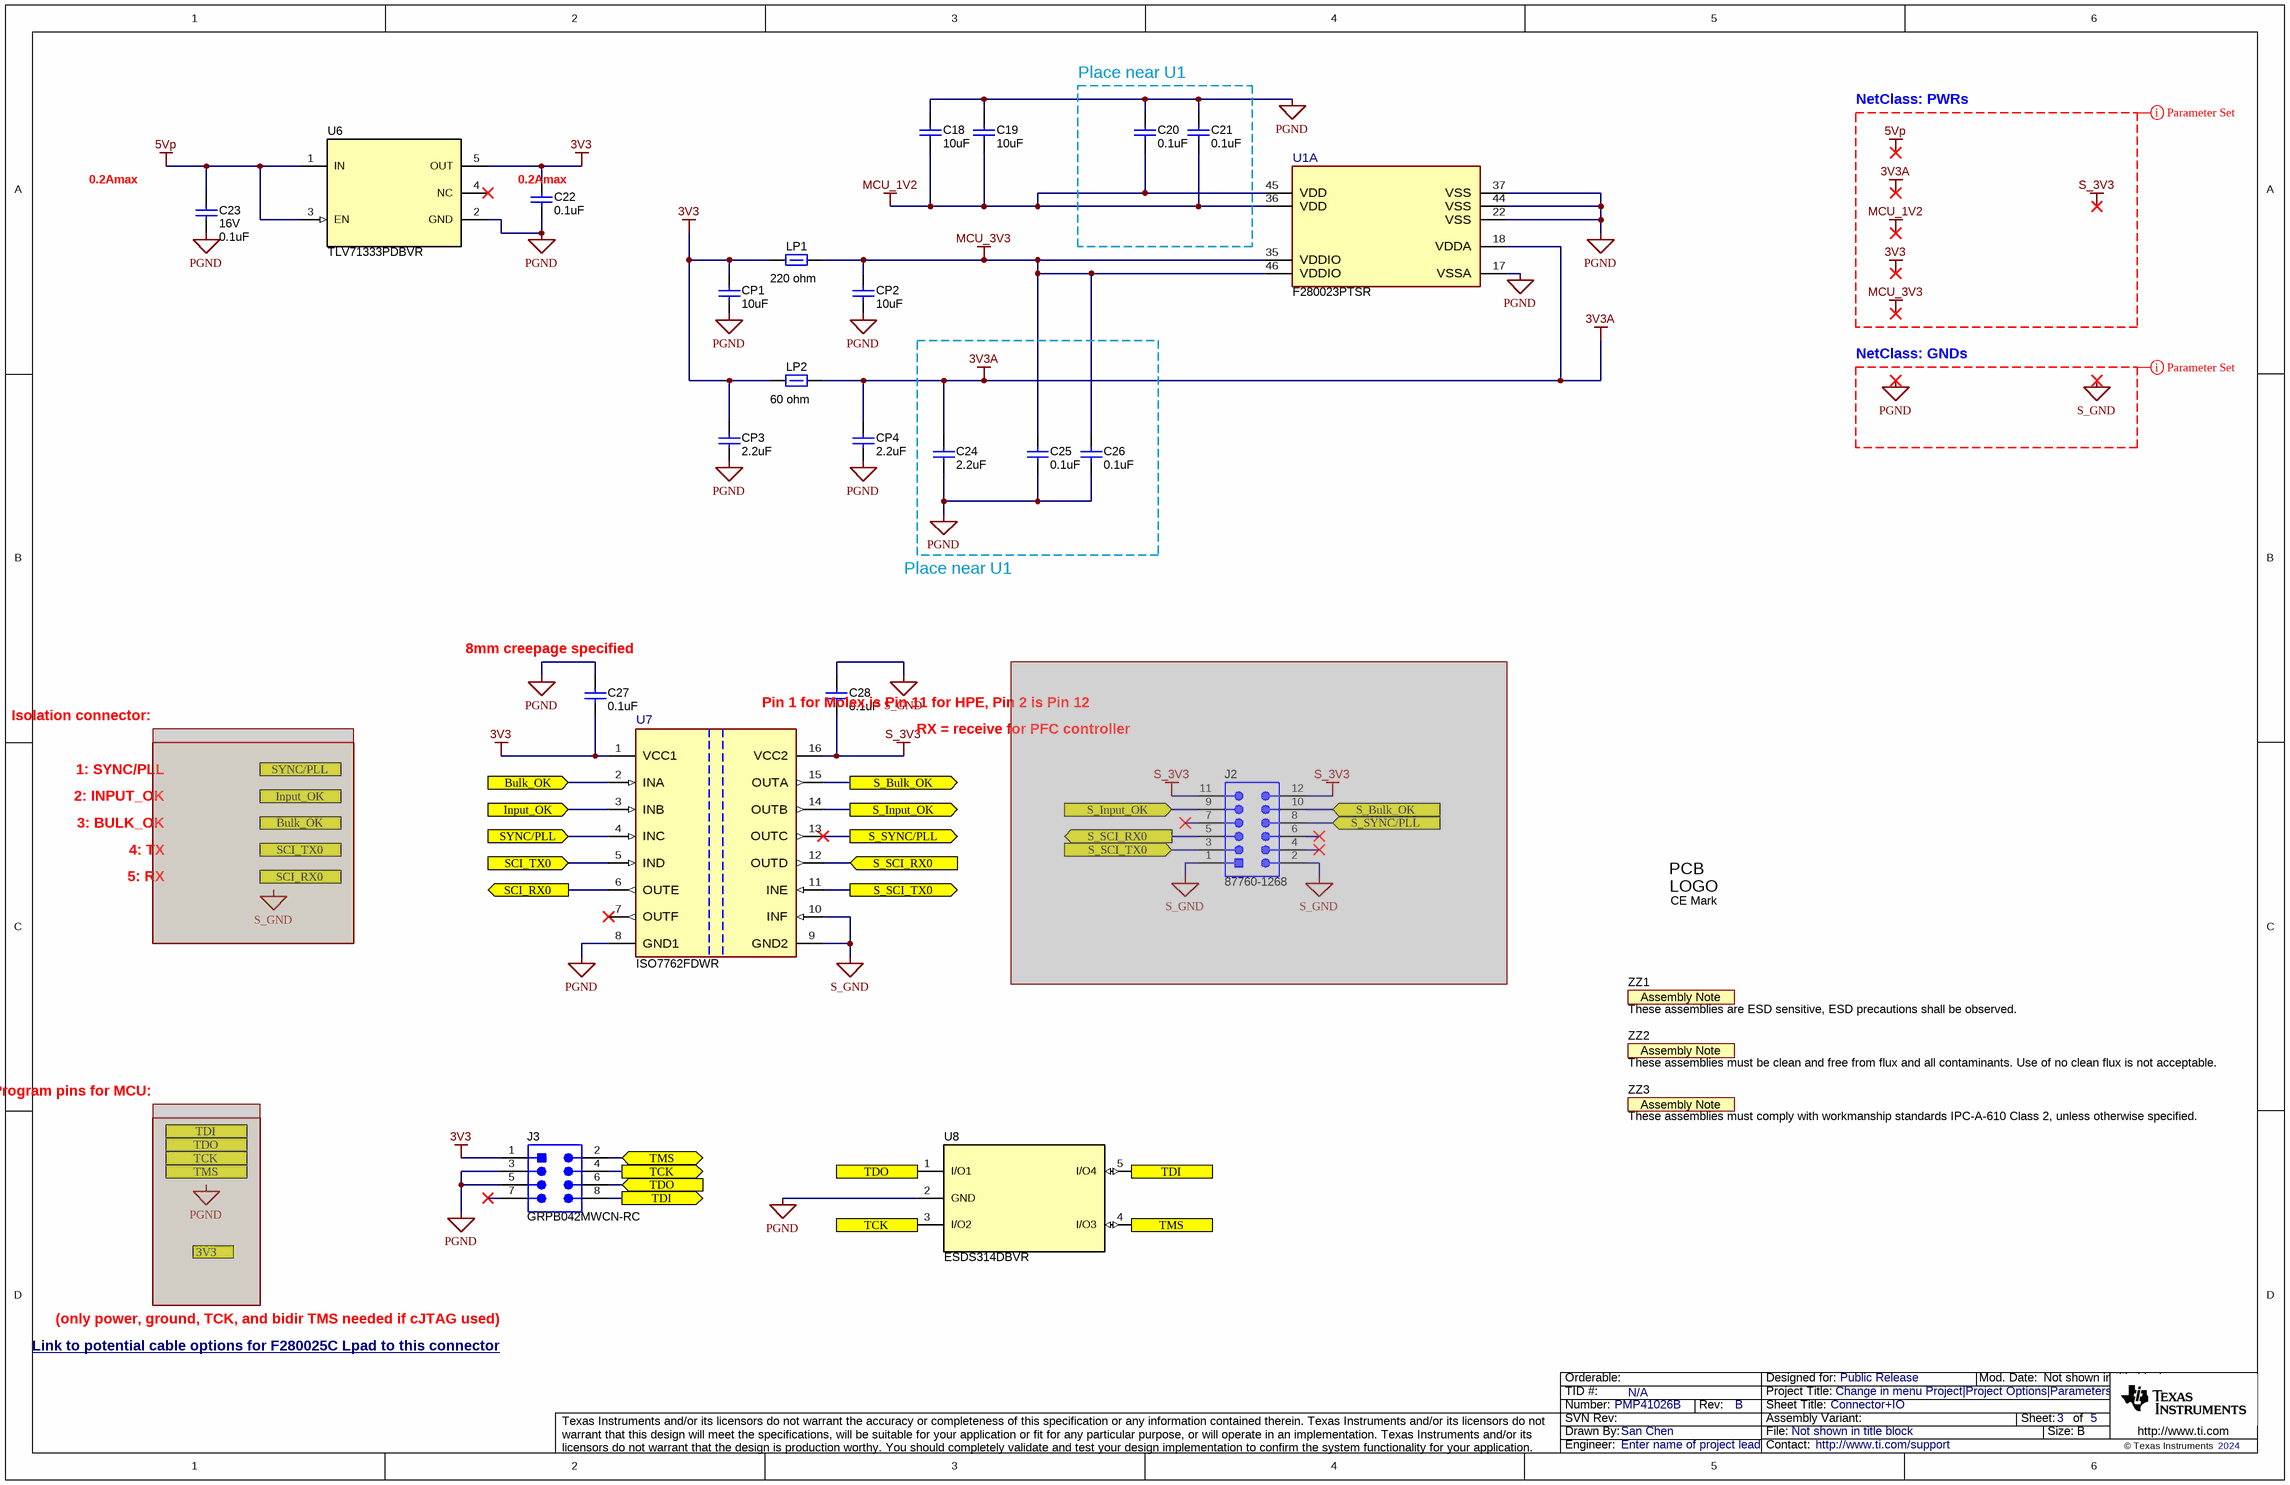
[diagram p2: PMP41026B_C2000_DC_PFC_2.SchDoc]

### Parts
C18  ValueDisplayed: 10uF  [0603]  (hidden comment: GRM188R61A106ME69D)
C19  ValueDisplayed: 10uF  [0603]  (hidden comment: GRM188R61A106ME69D)
C20  ValueDisplayed: 0.1uF  [0402]  (hidden comment: GRM155R71A104KA01D)
C21  ValueDisplayed: 0.1uF  [0402]  (hidden comment: GRM155R71A104KA01D)
C22  ValueDisplayed: 0.1uF  [0402]  (hidden comment: GRM155R70J104KA01D)
C23  VDC_V: 16V  ValueDisplayed: 0.1uF  [0402]  (hidden comment: GRM155R71C104KA88D)
C24  ValueDisplayed: 2.2uF  [0603]  (hidden comment: C0603C225K8PACTU)
C25  ValueDisplayed: 0.1uF  [0402]  (hidden comment: GRM155R71A104KA01D)
C26  ValueDisplayed: 0.1uF  [0402]  (hidden comment: GRM155R71A104KA01D)
C27  ValueDisplayed: 0.1uF  [0402]  (hidden comment: GRM155R71A104KA01D)
C28  ValueDisplayed: 0.1uF  [0402]  (hidden comment: GRM155R71A104KA01D)
CP1  ValueDisplayed: 10uF  [0805_HV]  (hidden comment: LMK212ABJ106KG-T)
CP2  ValueDisplayed: 10uF  [0805_HV]  (hidden comment: LMK212ABJ106KG-T)
CP3  ValueDisplayed: 2.2uF  [0603]  (hidden comment: CGA3E3X5R1A225K080AB)
CP4  ValueDisplayed: 2.2uF  [0603]  (hidden comment: CGA3E3X5R1A225K080AB)
J2  87760-1268  [Molex_87760-1268]  (masked out: inside a compile mask, not in the netlist)
J3  GRPB042MWCN-RC  [Sullins_GRPB042MWCN]
Logo1  CE Mark  [CE_Mark_5mm]  (no BOM)
LP1  value 220 ohm  [0805_HV]  (hidden comment: BLM21PG221SN1D)
LP2  value 60 ohm  [0805_HV]  (hidden comment: 742792063)
U1  F280023PTSR  [PT0048A-IPC_C]  (part A of 4)
U6  TLV71333PDBVR  [DBV0005A_N]
U7  ISO7762FDWR  [DW0016B-MFG]
U8  ESDS314DBVR  [DBV0005A_N]
ZZ1  These assemblies are ESD sensitive, ESD precautions shall be observed.  [AssemblyNote]  (no BOM)
ZZ2  These assemblies must be clean and free from flux and all contaminants. Use of no clean flux is not acceptable.  [AssemblyNote]  (no BOM)
ZZ3  These assemblies must comply with workmanship standards IPC-A-610 Class 2, unless otherwise specified.  [AssemblyNote]  (no BOM)

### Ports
3V3 (in), Bulk_OK (in), Input_OK (in), Input_OK (out), S_Bulk_OK (in), S_Bulk_OK (out), S_Input_OK (in), S_Input_OK (out), S_SCI_RX0 (in), S_SCI_RX0 (out), S_SCI_TX0 (in), S_SCI_TX0 (out), S_SYNC/PLL (in), S_SYNC/PLL (out), SCI_RX0 (in), SCI_RX0 (out), SCI_TX0 (in), SCI_TX0 (out), SYNC/PLL (in), SYNC/PLL (out), TCK, TCK (out), TDI, TDI (in), TDI (out), TDO, TDO (in), TDO (out), TMS, TMS (bidir), TMS (out)

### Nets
3V3: C22.1 C27.2 CP1.2 CP3.2 J3.1 LP1.1 LP2.1 U6.5(OUT) U7.1(VCC1)
3V3A: C24.2 CP4.2 LP2.2 U1.18(VDDA)
5Vp: C23.1 U6.1(IN) U6.3(EN)
MCU_1V2: C18.1 C19.1 C20.2 C21.2 U1.36(VDD) U1.45(VDD)
MCU_3V3: C25.1 C26.1 CP2.2 LP1.2 U1.35(VDDIO) U1.46(VDDIO)
PGND: C18.2 C19.2 C20.1 C21.1 C22.2 C23.2 C24.1 C25.2 C26.2 C27.1 CP1.1 CP2.1 CP3.1 CP4.1 J3.3 J3.5 U1.17(VSSA) U1.22(VSS) U1.37(VSS) U1.44(VSS) U6.2(GND) U7.8(GND1) U8.2(GND)
S_3V3: C28.2 U7.16(VCC2)
S_GND: C28.1 U7.9(GND2) U7.10(INF)  [project net S_AGND]
Bulk_OK: U7.2(INA) ; port Bulk_OK
Input_OK: U7.3(INB) ; port Input_OK
PFC_OK_s: U7.15(OUTA) ; port S_Bulk_OK
S_SYNC/PLL: U7.13(OUTC) ; port S_SYNC/PLL
SCI_RX0: U7.6(OUTE) ; port SCI_RX0
SCI_TX0: U7.5(IND) ; port SCI_TX0
SYNC/PLL: U7.4(INC) ; port SYNC/PLL
TCK: J3.4 U8.3(I/O2) ; port TCK
TDI: J3.8 U8.5(I/O4) ; port TDI
TDO: J3.6 U8.1(I/O1) ; port TDO
TMS: J3.2 U8.4(I/O3) ; port TMS
URAT1_RX_s: U7.12(OUTD) ; port S_SCI_RX0
URAT1_TX_s: U7.11(INE) ; port S_SCI_TX0
VINOK-s: U7.14(OUTB) ; port S_Input_OK

Not connected (* = marked no-connect by the designer): J3 7*; U6 4(NC)*; U7 7(OUTF)*

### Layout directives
net class PWRs: 3V3, 3V3A, 5Vp, MCU_1V2, MCU_3V3, S_3V3
net class GNDs: PGND, S_GND

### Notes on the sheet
- Place near U1
- NetClass: PWRs
- (near C23) 0.2Amax
- (near C22) 0.2Amax
- NetClass: GNDs
- 8mm creepage specified
- Pin 1 for Molex is Pin 11 for HPE, Pin 2 is Pin 12
- Isolation connector:
- 1: SYNC/PLL
- RX = receive for PFC controller
- 2: INPUT_OK
- 3: BULK_OK
- 4: TX
- 5: RX
- Program pins for MCU:
- (only power, ground, TCK, and bidir TMS needed if cJTAG used)
- Link to potential cable options for F280025C Lpad to this connector <https://www.digikey.com/en/products/filter/rectangular-cable-assemblies/450?s=N4IgjCBcoBw1oDGUBmBDANgZwKYBoQB7KAbRADYBmAThnJAF0CAHAFyhAGVWAnASwB2AcxABfUQQBMpEADFZnACKNRQA>
- Labels drawn without touching a wire or pin: 3V3, 3V3A, 5Vp, MCU_1V2, MCU_3V3, PGND, S_3V3, S_GND

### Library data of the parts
C18 C19 = CMP-0007318-5: CAP, CERM, 10 uF, 10 V, +/- 20%, X5R, 0603; Manufacturer: MuRata; Polarized: N; Value: 10uF; U/M: EA; Cap_F: 10µF; Value1: Unknown; VDC_V: 10V; TaMin_C: -55°C; TaMax_C: 85°C; AEC Category: Q200; SizeArea_mm2: 1.28; SizeAreaWB_mm2: 4.68; SizeX_mm: 1.6; SizeY_mm: 0.8; SizeZ_mm: 1
C20 C21 C25-C28 = CMP-0006629-2: as C11 on sheet PMP41026B_C2000_DC_PFC_1
C22 = CMP-0006623-2: CAP, CERM, 0.1 uF, 6.3 V, +/- 10%, X7R, 0402; Manufacturer: MuRata; Polarized: N; Value: 0.1uF; U/M: EA; Cap_F: 100nF; Value1: Unknown; VDC_V: 6.3V; TaMin_C: -55°C; TaMax_C: 125°C; AEC Category: Q200; SizeArea_mm2: 0.5; SizeAreaWB_mm2: 3; SizeX_mm: 1; SizeZ_mm: 0.6
C23 = CMP-0006641-2: CAP, CERM, 0.1 uF, 16 V, +/- 10%, X7R, 0402; Manufacturer: MuRata; TaMin_C: -55°C; Polarized: N; SizeAreaWB_mm2: 3; Value1: Unknown; U/M: EA; Value: 0.1uF; TaMax_C: 125°C; SizeZ_mm: 0.6; SizeX_mm: 1; SizeY_mm: 0.5; Cap_F: 100nF; AEC Category: Q200
C24 = CMP-0006906-5: as C1 on sheet PMP41026B_C2000_DC_PFC_1
CP1 CP2 = CMP-0008395-2: CAP, CERM, 10 uF, 10 V, +/- 10%, X5R, 0805; Manufacturer: Taiyo Yuden; Polarized: N; Value: 10uF; U/M: EA; Cap_F: 10µF; Value1: Unknown; VDC_V: 10V; TaMin_C: -55°C; TaMax_C: 85°C; Cap_Case: 0805; AEC Category: Q200; SizeArea_mm2: 2.5; SizeAreaWB_mm2: 6.75; SizeX_mm: 2; SizeY_mm: 1.25; SizeZ_mm: 1.45
CP3 CP4 = CMP-0007091-5: CAP, CERM, 2.2 uF, 10 V, +/- 10%, X5R, AEC-Q200 Grade 3, 0603; Manufacturer: TDK; Polarized: N; Value: 2.2uF; U/M: EA; Cap_F: 2.2µF; Value1: Unknown; VDC_V: 10V; TaMin_C: -55°C; TaMax_C: 85°C; AEC Category: Q200; AEC Qualified: Y; AEC Grade: 3; SizeArea_mm2: 1.28; SizeAreaWB_mm2: 4.68; SizeX_mm: 1.6; SizeY_mm: 0.8; SizeZ_mm: 1
J2 = CMP-0055329-2: Header, 2mm, 6x2, Tin, R/A, TH; Manufacturer: Molex; Current_A: 2A; Shrouded: N; Gender: Male; Cert_CSA: Y; Voltage_V: 125V; Row_Count: 2
J3 = CMP-0086278-1: Header, 1.27mm, 4x2, Gold, R/A, TH; Manufacturer: Sullins Connector Solutions; Current_A: 1A; Shrouded: N; Pitch_mm: 1.27; Voltage_V: 500V; Gender: Male; Row_Count: 2
Logo1 = CMP-0074838-1: Texas Instrument Corporate Signature; PartNumber: Texas Instruments; SymbolCreator: a0412235; Lib Reference: TI_Logo; Library Reference: Logo
LP1 = CMP-0003363-1: Ferrite Bead, 220 ohm @ 100 MHz, 2 A, 0805; Manufacturer: MuRata; Imax_A: 2A; DCR_ohm: 0.045; Value1: 0.045 ohm; ZTyp@100MHz_Ohm: 220; SizeArea_mm2: 2.5; SizeAreaWB_mm2: 6.75; SizeX_mm: 2; SizeY_mm: 1.25; SizeZ_mm: 1.45
LP2 = CMP-0003093-1: Ferrite Bead, 60 ohm @ 100 MHz, 3 A, 0805; Manufacturer: Wurth Elektronik; Ztyp@1GHz_Ohm: 95.384; ZTyp@100MHz_Ohm: 60; SizeAreaWB_mm2: 6.75; DCR_ohm: 0.025; Value1: 0.025 ohm; Imax_A: 3A; SizeZ_mm: 1.45; SizeX_mm: 2; SizeY_mm: 1.25; SizeArea_mm2: 2.5
U1 = CMP-0088708-1: as U1 on sheet PMP41026B_C2000_DC_PFC_1
U6 = CMP-0066771-1: 150-mA, Low-Dropout Regulator with Foldback Current Limit for Portable Devices, DBV0005A (SOT-23-5); Alternate PartNumber: TLV71333PDBVT; Alternate Manufacturer: Texas Instruments; Green_Lifecycle: Active; SizeAreaWB_mm2: 14.82; Green_REACh: Passed; U/M: EA; SizeZ_mm: 1.45; SizeX_mm: 2.8; SizeY_mm: 2.9; SizeArea_mm2: 8.12; CompType: IC
U7 = CMP-0092396-1: General Purpose Digital Isolator 5000Vrms 6 Channel 100Mbps 85kV/µs CMTI 16-SOIC (0.295", 7.50mm Width); Manufacturer: Texas Instruments; TaMin_C: -55°C; TaMax_C: +125°C; Nominal Supply Current: 2.1-25.7mA; SizeZ_mm: 2.65mm; AEC Qualified: No; Max Supply Voltage: 5.5V; Min Supply Voltage: 2.25V; Standoff Height: 0.1mm; Interface: SPI,CAN; TJmax_C: +150°C
U8 = CMP-0085635-1: Data-Line Surge and ESD Protection Diode Array, DBV0005A (SOT-23-5); Alternate Manufacturer: Texas Instruments; CompType: IC; SizeX_mm: 2.8; Rating: Catalog; AEC Category: Q200; SizeZ_mm: 1.45; SizeArea_mm2: 8.12; AEC Qualified: N; SizeAreaWB_mm2: 14.82; SizeY_mm: 2.9
ZZ1 = CMP-0077236-1
ZZ2 = CMP-0077237-1
ZZ3 = CMP-0077238-1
